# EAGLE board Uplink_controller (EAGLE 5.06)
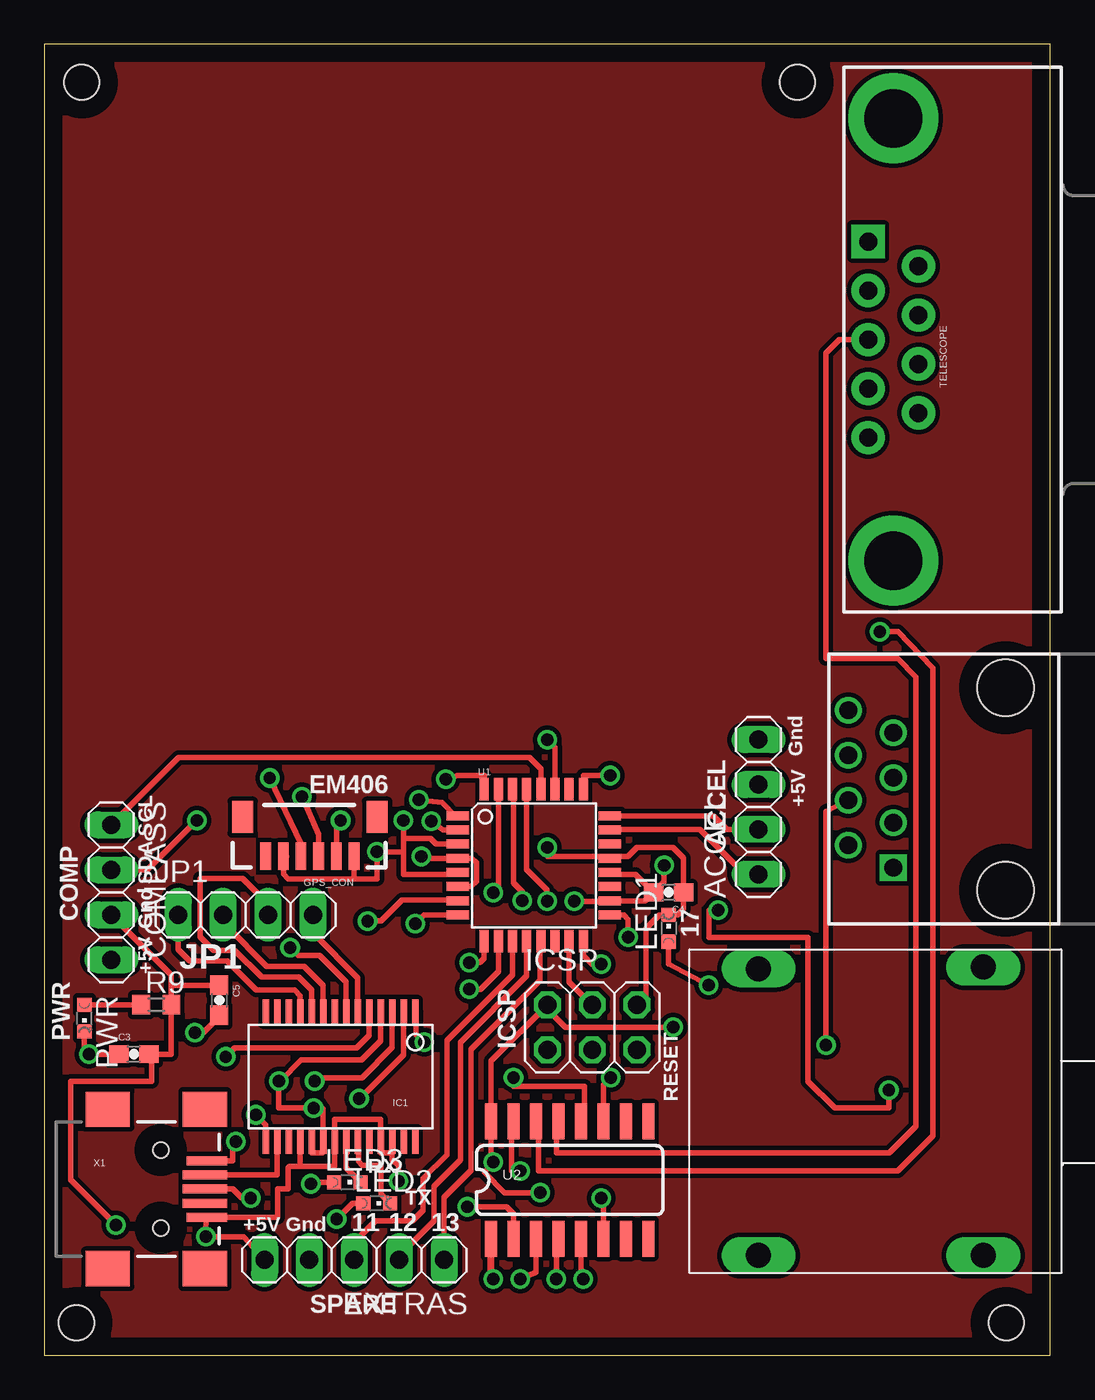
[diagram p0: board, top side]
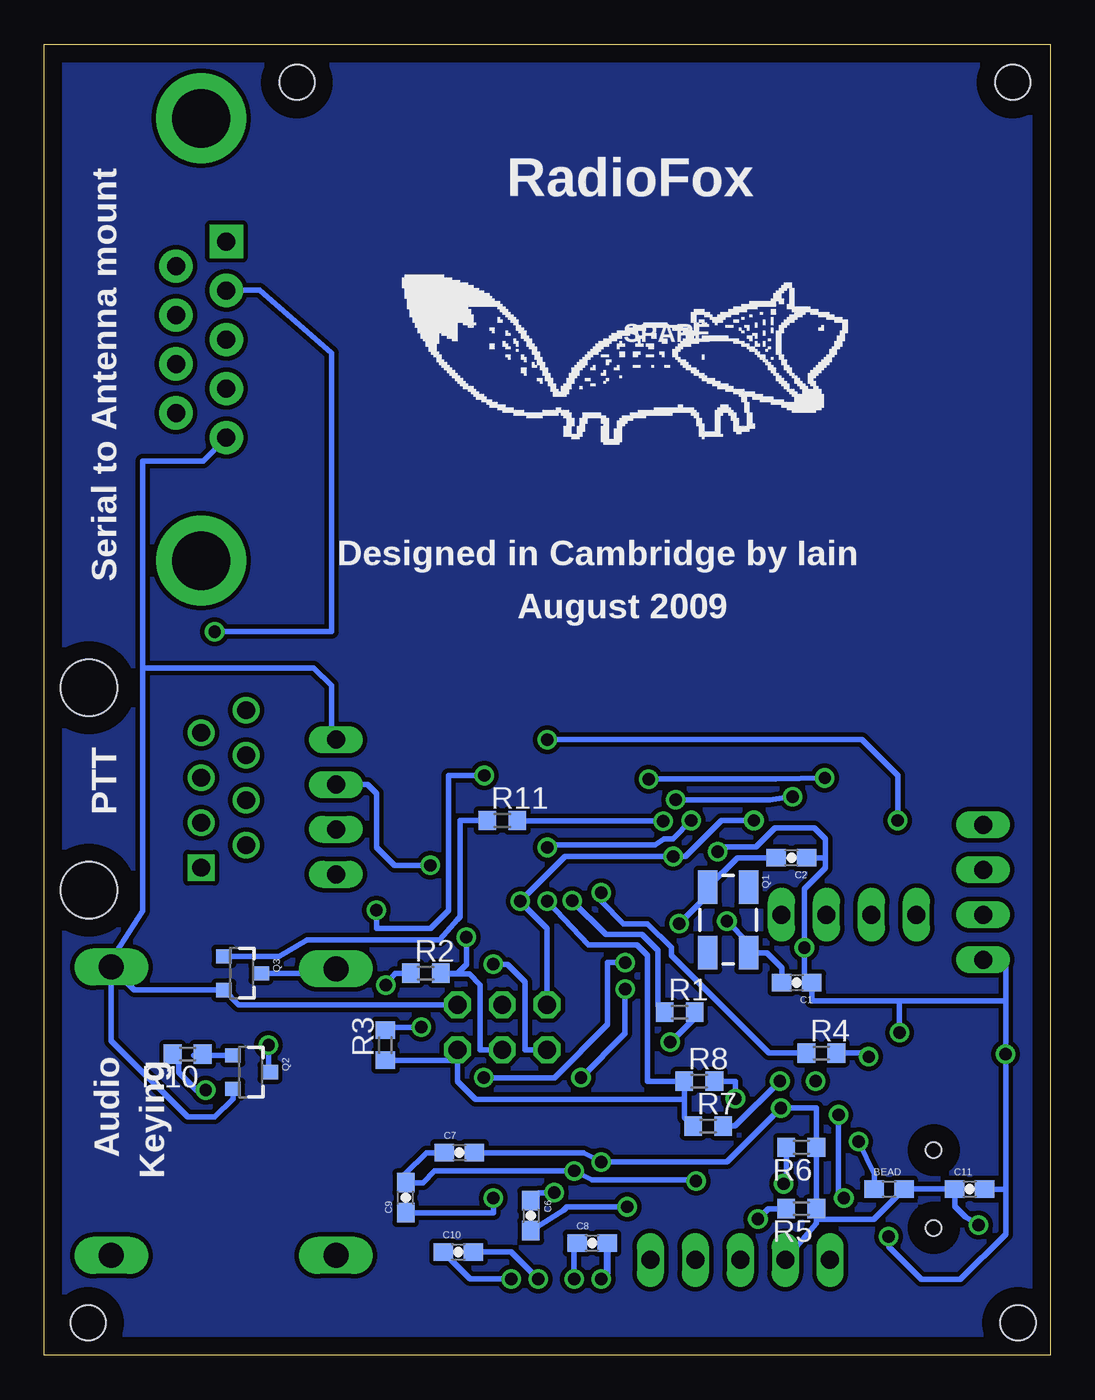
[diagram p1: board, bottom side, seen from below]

Size 56.86 x 74.09 mm. Coordinates in mm from the lower left corner, seen from the top.
Outline: 0,0 56.86,0 56.86,74.09 0,74.09 0,0
Copper layers (1*16): Top 0.035mm / dielectric 1.5mm / Bottom 0.035mm
Design rules "olimex10mils": minimum track width 10mil, minimum drill 24mil, track to track 10mil, track to pad 10mil, pad to pad 10mil, via to via 10mil, smd to smd 10mil, copper to edge 40mil, drill to drill 10mil, minimum pad ring 10mil, minimum via ring 8mil, stop-mask expansion 0mil, vias tented up to drill 0mil, thermal gap 10mil
Holes 2 mm at 42.57,71.94 54.37,1.84 1.82,1.84 2.12,71.94

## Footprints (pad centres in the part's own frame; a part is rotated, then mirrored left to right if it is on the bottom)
1X04 = drill 1.016 long: 1 -3.81,0; 2 -1.27,0; 3 1.27,0; 4 3.81,0
0603 = smd 1.1 x 1: 1 -0.85,0; 2 0.85,0
0603-CAP = smd 1.1 x 1: 1 -0.85,0; 2 0.85,0
1X05 = drill 1.016 long: 1 -5.08,0; 2 -2.54,0; 3 0,0; 4 2.54,0; 5 5.08,0
EM406 = smd 0.6 x 1.55: 1 0,0; 2 1,0; 3 2,0; 4 3,0; 5 4,0; 6 5,0 | smd 1.2 x 1.8: P$1 -1.3,-2.225; P$2 6.3,-2.225
SSOP28DB = smd 0.348 x 1.397: 1 -4.225,-3.656; 2 -3.575,-3.656; 3 -2.925,-3.656; 4 -2.275,-3.656; 5 -1.625,-3.656; 6 -0.975,-3.656; 7 -0.325,-3.656; 8 0.325,-3.656; 9 0.975,-3.656; 10 1.625,-3.656; 11 2.275,-3.656; 12 2.925,-3.656; 13 3.575,-3.656; 14 4.225,-3.656; 15 4.225,3.656; 16 3.575,3.656; 17 2.925,3.656; 18 2.275,3.656; 19 1.625,3.656; 20 0.975,3.656; 21 0.325,3.656; 22 -0.325,3.656; 23 -0.975,3.656; 24 -1.625,3.656; 25 -2.275,3.656; 26 -2.925,3.656; 27 -3.575,3.656; 28 -4.225,3.656
2X03 = drill 1.016 octagon: 1 -2.54,-1.27; 2 -2.54,1.27; 3 0,-1.27; 4 0,1.27; 5 2.54,-1.27; 6 2.54,1.27
AUDIO_JACK_NMJ4HFD2 = drill 1.4 long: 1 0,0; 2 12.7,0.1; 3 0,-16.2; 4 12.7,-16.2
CHIPLED_0603 = smd 0.8 x 0.8: A 0,-0.75; C 0,0.75
CRYSTAL-SMD-5X3 = smd 1.9 x 1.1: 1 -1.85,-1.15; 2 1.85,-1.15; 3 1.85,1.15; 4 -1.85,1.15
SOT23-3 = smd 0.8 x 0.9: 1 -0.95,-1; 2 0.95,-1; 3 0,1.1
R0603 = smd 1 x 1.1: 1 -0.85,0; 2 0.85,0
RJ45-8 = drill 1 square: 1 -4.445,6.35 | drill 1 round: 2 -3.175,8.89; 3 -1.905,6.35; 4 -0.635,8.89; 5 0.635,6.35; 6 1.905,8.89; 7 3.175,6.35; 8 4.445,8.89 | hole 3.2: -5.715,0; 5.715,0
DB9 = drill 1.016 pad 1.88 square: 1 -5.54,-1.42 | drill 1.016 pad 1.88 round: 2 -2.77,-1.42; 3 0,-1.42; 4 2.77,-1.42; 5 5.54,-1.42; 6 -4.15,1.42; 7 -1.38,1.42; 8 1.38,1.42; 9 4.15,1.42 | drill 3.302 pad 5.08 round: G1 -12.5,0; G2 12.5,0
TQFP32-08 = smd 1.27 x 0.508: 1 -4.293,2.8; 2 -4.293,2; 3 -4.293,1.2; 4 -4.293,0.4; 5 -4.293,-0.4; 6 -4.293,-1.2; 7 -4.293,-2; 8 -4.293,-2.8; 17 4.293,-2.8; 18 4.293,-2; 19 4.293,-1.2; 20 4.293,-0.4; 21 4.293,0.4; 22 4.293,1.2; 23 4.293,2; 24 4.293,2.8 | smd 0.508 x 1.27: 9 -2.8,-4.293; 10 -2,-4.293; 11 -1.2,-4.293; 12 -0.4,-4.293; 13 0.4,-4.293; 14 1.2,-4.293; 15 2,-4.293; 16 2.8,-4.293; 25 2.8,4.293; 26 2,4.293; 27 1.2,4.293; 28 0.4,4.293; 29 -0.4,4.293; 30 -1.2,4.293; 31 -2,4.293; 32 -2.8,4.293
SO016 = smd 0.66 x 2.032: 1 -4.445,-3.315; 2 -3.175,-3.315; 3 -1.905,-3.315; 4 -0.635,-3.315; 5 0.635,-3.315; 6 1.905,-3.315; 7 3.175,-3.315; 8 4.445,-3.315; 9 4.445,3.315; 10 3.175,3.315; 11 1.905,3.315; 12 0.635,3.315; 13 -0.635,3.315; 14 -1.905,3.315; 15 -3.175,3.315; 16 -4.445,3.315
USB-MINIB = smd 2.5 x 0.5: D+ 2.5,0; D- 2.5,0.8; ID 2.5,-0.8 | smd 2.3 x 0.5: GND 2.6,-1.6; VBUS 2.6,1.6 | smd 2.5 x 2: GND@1 -3,-4.5; GND@2 -3,4.5; GND@3 2.5,4.5; GND@4 2.5,-4.5 | hole 0.9: 0,2.2; 0,-2.2

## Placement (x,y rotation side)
ACCEL  [1X04]  40.37,30.99 90 top
BEAD  [0603]  9.11,9.4 0 bottom
C1  22p  [0603-CAP]  14.33,21.05 180 bottom
C2  22p  [0603-CAP]  14.63,28.11 180 bottom
C3  100n  [0603-CAP]  5.06,17.02 0 top
C4  100n  [0603-CAP]  35.29,26.16 180 top
C5  10n  [0603-CAP]  9.89,20.06 270 top
C6  1u  [0603-CAP]  29.36,7.89 270 bottom
C7  1u  [0603-CAP]  33.39,11.45 0 bottom
C8  1u  [0603-CAP]  25.89,6.34 0 bottom
C9  1u  [0603-CAP]  36.43,8.9 90 bottom
C10  1u  [0603-CAP]  33.46,5.84 0 bottom
C11  10u  [0603-CAP]  4.56,9.4 0 bottom
COMPASS  [1X04]  3.79,26.16 270 top
EXTRAS  [1X05]  17.52,5.39 180 top
GPS_CON  EM406  [EM406]  17.51,28.19 180 top
IC1  FT232RLSSOP  [SSOP28DB]  16.75,15.75 180 top
ICSP  [2X03]  30.97,18.54 0 top
JACK1  AUDIO_JACK  [AUDIO_JACK_NMJ4HFD2]  40.37,21.84 0 top
JP1  [1X04]  11.38,24.89 0 top
LED1  [CHIPLED_0603]  35.29,24.13 0 top
LED2  [CHIPLED_0603]  18.79,8.59 270 top
LED3  [CHIPLED_0603]  17.14,9.78 270 top
PWR  [CHIPLED_0603]  2.27,19.05 180 top
Q1  16MHz  [CRYSTAL-SMD-5X3]  18.2,24.61 270 bottom
Q2  MOSFET-NCHANNELSMD  [SOT23-3]  45.2,16 270 bottom
Q3  MOSFET-NCHANNELSMD  [SOT23-3]  45.7,21.59 270 bottom
R1  1K  [R0603]  20.95,19.4 0 bottom
R2  1K  [R0603]  35.29,21.59 0 bottom
R3  10K  [R0603]  37.58,17.52 90 bottom
R4  1K  [R0603]  12.94,17.08 0 bottom
R5  1K  [R0603]  14.07,8.29 180 bottom
R6  1K  [R0603]  14.07,11.75 180 bottom
R7  100R  [R0603]  19.34,12.95 0 bottom
R8  100R  [R0603]  19.84,15.49 0 bottom
R9  1K  [R0603]  6.33,19.81 0 top
R10  1K  [R0603]  48.75,17.02 180 bottom
R11  1K  [R0603]  30.97,30.22 0 bottom
RADIO_MIKE  RJ45-8PTH  [RJ45-8]  54.34,32 90 top
TELESCOPE  [DB9]  47.99,57.4 270 top
U1  ATMEGA168  [TQFP32-08]  27.67,27.68 0 top
U2  MAX232SOIC16  [SO016]  29.7,9.9 0 top
U$7  EM406_OUTLINE  [EM406_OUTLINE]  not placed on the board
X1  USBSMD  [USB-MINIB]  6.59,9.4 0 top

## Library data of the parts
ACCEL COMPASS EXTRAS ICSP JP1 = pinhead
BEAD C1-C11 GPS_CON IC1 Q1-Q3 RADIO_MIKE TELESCOPE U1 U2 U$7 X1 = SparkFun
JACK1 = uplink_controller
LED1-LED3 PWR = led
R1-R11 = rcl

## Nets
5V: ACCEL.3 BEAD.2 C3.2 C4.2 C5.1 C6.1 C7.2 C11.1 COMPASS.3 EXTRAS.4 GPS_CON.2 IC1.4 IC1.19 IC1.20 ICSP.2 R3.2 R5.1 R6.1 R9.2 U1.4 U1.6 U1.18 U1.20 U2.16
EXTRA1: EXTRAS.3 U1.11
EXTRA2: EXTRAS.2 U1.12
EXTRA3: EXTRAS.1 U1.13
GND: ACCEL.4 C1.1 C2.1 C3.1 C4.1 C5.2 C7.1 C9.2 C11.2 COMPASS.4 EXTRAS.5 GPS_CON.1 GPS_CON.5 IC1.7 IC1.18 IC1.21 IC1.25 IC1.26 ICSP.6 JACK1.2 LED1.C PWR.C Q2.2 Q3.2 TELESCOPE.5 U1.3 U1.5 U1.21 U2.15 X1.GND
GPS_ATM168_RX: GPS_CON.4 U1.32
GPS_ATM168_TX: GPS_CON.3 U1.1
KEY_OUT: R11.2 U1.2
N$1: C1.2 Q1.3 U1.7
N$2: C2.2 Q1.1 U1.8
N$3: ICSP.1 U1.16
N$4: LED1.A R2.1
N$5: ICSP.3 R2.2 U1.17
N$6: IC1.1 R1.2
N$7: IC1.5 R4.2
N$8: LED2.A R5.2
N$9: IC1.23 LED2.C
N$10: IC1.22 LED3.C
N$11: LED3.A R6.2
N$12: IC1.16 X1.D-
N$13: IC1.15 X1.D+
N$14: TELESCOPE.3 U2.13
N$15: IC1.6 JP1.4
N$16: IC1.10 JP1.3
N$17: IC1.9 JP1.2
N$18: IC1.11 JP1.1
N$19: IC1.3 R7.2
N$20: IC1.2 R8.2
N$21: Q2.3 RADIO_MIKE.4
N$22: JACK1.1 Q3.3
N$23: ICSP.4 U1.15
N$24: PWR.A R9.1
N$25: Q2.1 R10.1
N$26: C8.2 U2.1
N$27: COMPASS.1 U1.28
N$28: COMPASS.2 U1.27
N$29: C8.1 U2.3
N$30: ACCEL.1 U1.23
N$31: C10.2 U2.4
N$32: C10.1 U2.5
N$33: C9.1 U2.6
N$34: C6.2 U2.2
N$35: Q3.1 R11.1
N$36: BEAD.1 X1.VBUS
N$39: U1.26
N$40: U1.19
N$41: U1.22
N$42: ACCEL.2 U1.24
PTT: R10.2 U1.25
RAND: TELESCOPE.2 U2.14
RESET: ICSP.5 R3.1 R7.1 R8.1 U1.29
SERIAL_RX: R4.1 U1.31
SERIAL_TX: R1.1 U1.30
TELESC_ATM168_RX: U1.10 U2.12
TELESC_ATM168_TX: U1.9 U2.11

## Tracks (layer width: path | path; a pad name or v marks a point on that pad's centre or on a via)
5V  (via drill 0.7)
  Top 0.305: IC1.19 15.12,11.43 15.73,11.43 15.73,12.09 IC1.20 15.77,13.93 v15.22,13.97 13.26,13.97 v13.26,15.49 13.33,15.49 14.52,16.69 17.94,16.69 19.02,17.77 IC1.4 | v29.96,25.65 31.93,25.65 arc90 U1.18 33.96,25.68 C4.2 | v21.32,28.19 21.72,28.08 U1.4 24.18,28.08 24.42,27.84 24.42,26.79 24.12,26.49 U1.6 | GPS_CON.2 16.51,30.22 v16.75,30.22 | v35.54,18.54 29.45,18.54 28.43,19.56 ICSP.2 25.26,16.63 U2.16 25.26,11.04 v25.38,10.92 24.88,10.34 26.02,9.19 v28.02,9.19 | R9.2 7.18,20.91 | 7.18,20.91 C5.1 | R9.2 7.44,19.56 | v4.05,7.36 1.51,9.9 1.51,15.49 6.08,15.49 6.08,17.02 C3.2 7.18,17.02 R9.2 | COMPASS.3 7.18,21.5 7.18,20.91 | U1.20 32.07,27.18 33.42,27.18 C4.2 | C4.2 35.04,26.76 v35.04,27.68
  Bottom 0.305: C7.2 26.38,11.45 v25.38,10.92 18.27,10.92 v15.22,13.97 13.22,13.97 R6.1 R5.1 | ICSP.2 28.43,24.13 v29.96,25.65 27.42,28.19 v21.32,28.19 20.62,28.19 18.59,30.22 v16.75,30.22 | R3.2 37.41,18.54 v35.54,18.54 | v35.04,27.68 37.07,27.68 38.08,28.7 38.08,31.75 38.59,32.26 ACCEL.3 | v4.05,7.36 4.81,7.81 5.41,8.41 C11.1 | R5.1 13.22,7.69 9.97,7.69 BEAD.2 C11.1 | C6.1 28.91,9.19 v28.02,9.19 | EXTRAS.4 13.22,7.45 R5.1 | C11.1 5.15,9.14
EXTRA1
  Top 0.305: U1.11 26.47,21.48 22.77,17.79 22.77,11.34 21.42,9.99 21.42,8.19 20.82,7.59 18.72,7.59 17.82,6.69 17.82,5.99 EXTRAS.3
EXTRA2
  Top 0.305: U1.12 27.27,21.43 23.52,17.69 23.52,11.04 22.02,9.54 22.02,7.59 20.12,5.69 EXTRAS.2 20.02,5.73
EXTRA3
  Top 0.305: U1.13 28.02,23.39 28.02,21.19 24.12,17.29 24.12,10.44 22.6,8.92 EXTRAS.1
GND  (via drill 0.7)
  Top 0.305: 14.47,10.69 IC1.18 | 19.67,11.43 19.02,11.43 IC1.25 19.02,13.34 16.42,13.34 IC1.21 16.42,10.69 14.47,10.69 | 19.67,11.43 IC1.26 | U2.15 26.4,13.09 26.4,10.42 v26.9,10.42 | 19.67,11.43 19.67,11.04 20.02,10.69 v20.02,9.84 | ICSP.6 34.02,20.32 34.02,24.13 34.77,24.88 LED1.C 35.79,24.88 36.14,25.23 C4.1 36.14,28.1 35.54,28.7 33.51,28.7 33,28.19 32.07,28.19 U1.21 31.96,28.19 28.43,28.19 v28.43,28.7 | 17.51,26.92 GPS_CON.1 | 20.3,28.44 20.3,29.21 | 20.3,28.44 20.3,27.18 23.27,27.18 U1.5 | 20.3,29.21 21.83,29.21 22.15,28.88 U1.3 | 20.3,29.21 v20.3,30.22 | PWR.C 2.27,17.02 v2.52,17.02 C3.1 | GPS_CON.5 13.7,28.19 13.52,28.02 13.52,27.19 13.79,26.92 17.51,26.92 | C5.2 9.98,19.21 9,18.24 v8.52,18.24 | EXTRAS.5 11.28,6.71 v9.13,6.71 9.09,6.9 X1.GND 13.19,7.8 13.19,9.4 13.77,9.4 13.77,10.59 13.87,10.69 14.47,10.69 | 20.3,28.44 18.83,28.44 v18.8,28.47 18.8,26.92 17.51,26.92 | IC1.7 17.07,21.09 15.57,22.59 14.34,22.59 v13.9,23.03
  Bottom 0.305: JACK1.2 51.77,20.64 Q3.2 45.88,19.81 ICSP.6 | Q2.2 46.2,14.49 47.23,13.46 48.75,13.46 53.07,17.78 JACK1.2 | COMPASS.4 2.52,22.35 2.52,20.04 | 2.52,20.04 v2.52,17.02 2.52,9.39 | TELESCOPE.5 47.89,50.54 51.3,50.54 51.3,38.85 | 51.3,38.85 51.3,25.12 53.07,22.35 JACK1.2 | ACCEL.4 40.62,35.05 40.62,37.84 41.63,38.85 51.3,38.85 | v9.13,6.71 9.13,6.14 7.27,4.29 5.07,4.29 2.52,6.84 2.52,9.39 | C7.1 35.26,11.45 36.43,10.28 C9.2 35.46,9.75 34.79,10.42 v26.9,10.42 25.9,9.92 20.02,9.92 v20.02,9.84 | 12.72,28.14 12.72,27.54 13.9,26.36 v13.9,23.03 13.9,21.36 13.48,20.94 | 12.72,28.14 12.72,29.19 13.32,29.79 15.57,29.79 16.62,28.74 18.53,28.74 v18.8,28.47 | C2.1 12.75,28.11 12.72,28.14 | 13.48,20.94 C1.1 | 13.48,20.94 13.47,20.94 | C11.2 2.52,9.39 | v28.43,28.7 28.28,28.85 22.34,28.85 21.85,29.19 21.34,29.19 v20.3,30.22 | 13.48,20.94 13.48,20.04 8.52,20.04 | 2.52,20.04 8.52,20.04 | 8.52,20.04 v8.52,18.24
GPS_ATM168_RX  (via drill 0.7)
  Top 0.305: GPS_CON.4 14.51,28.91 v12.74,32.62 | v22.69,32.56 23.35,32.76 24.88,32.76 24.87,32.76 U1.32
  Bottom 0.305: v22.69,32.56 15.52,32.56 v12.74,32.62
GPS_ATM168_TX  (via drill 0.7)
  Top 0.305: GPS_CON.3 15.51,29.43 v14.57,31.57 | v21.17,31.39 22.47,31.24 23.23,30.48 U1.1
  Bottom 0.305: v21.17,31.39 15.88,31.39 v14.57,31.57
KEY_OUT  (via drill 0.7)
  Top 0.305: U1.2 22.53,29.68 v21.87,30.19
  Bottom 0.305: v21.87,30.19 30.09,30.19 R11.2
N$1  (via drill 0.7)
  Top 0.305: U1.7 23.32,25.74 20.22,25.74 19.02,24.54 v18.27,24.54
  Bottom 0.305: C1.2 15.18,21.89 16.02,22.74 17.03,22.74 Q1.3 17.05,23.31 v18.27,24.54
N$2  (via drill 0.7)
  Top 0.305: v20.97,24.39 21.47,24.88 U1.8
  Bottom 0.305: C2.2 17.69,28.11 Q1.1 19.35,26.01 v20.97,24.39
N$3  (via drill 0.7)
  Top 0.305: U1.16 30.46,22.6 30.97,22.1 v31.48,22.1
  Bottom 0.305: ICSP.1 29.67,17.27 29.67,21.09 30.68,22.1 v31.48,22.1
N$4  (via drill 0.7)
  Top 0.305: LED1.A 35.29,22.11 v37.56,20.91
  Bottom 0.305: v37.56,20.91 37.04,21.59 R2.1
N$5  (via drill 0.7)
  Top 0.305: v33,23.62 33,24.64 32.76,24.88 U1.17
  Bottom 0.305: v33,23.62 33,22.1 33.51,21.59 R2.2 34.39,21.54 32.82,21.54 32.22,20.94 32.22,17.27 ICSP.3
N$6  (via drill 0.7)
  Top 0.305: IC1.1 21.02,19.4 21.02,18.14 v21.47,17.69
  Bottom 0.305: R1.2 20.1,19.07 v21.47,17.69
N$7  (via drill 0.7)
  Top 0.305: v10.26,16.87 10.76,17.37 17.66,17.37 18.37,18.09 IC1.5
  Bottom 0.305: v10.26,16.87 10.47,17.08 R4.2
N$8  (via drill 0.7)
  Top 0.305: LED2.A 17.42,8.59 v16.52,7.69
  Bottom 0.305: R5.2 15.92,8.29 v16.52,7.69
N$9
  Top 0.305: IC1.23 17.72,11.43 17.76,11.43 17.76,10.95 17.97,10.74 18.97,10.74 19.02,10.69 19.02,9.1 LED2.C
N$10
  Top 0.305: IC1.22 17.07,10.59 LED3.C
N$11  (via drill 0.7)
  Top 0.305: LED3.A 15.16,9.78 v15.07,9.69
  Bottom 0.305: R6.2 14.92,9.84 v15.07,9.69
N$12
  Top 0.305: 13.17,11.43 13.17,10.67 | 13.17,11.43 IC1.16 | X1.D- 13.17,10.2 13.17,11.43
N$13  (via drill 0.7)
  Top 0.305: X1.D+ 10.65,9.4 11.16,8.89 v11.67,8.89 | IC1.15 12.52,13.03 v11.97,13.59
  Bottom 0.305: v11.97,13.59 11.97,9.19 v11.67,8.89
N$14
  Top 0.305: U2.13 28.94,13.09 28.94,11.43 47.75,11.43 49.27,12.94 49.27,38.34 48.24,39.37 44.18,39.37 44.18,56.64 44.94,57.4 TELESCOPE.3
N$15
  Top 0.305: IC1.6 17.72,21.34 15.27,23.79 15.27,24.81 JP1.4
N$16
  Top 0.305: IC1.10 15.12,20.64 14.37,21.39 12.27,21.39 10.77,22.89 9.57,22.89 8.82,23.64 8.82,26.94 11.22,26.94 12.72,25.44 12.72,24.96 JP1.3
N$17
  Top 0.305: IC1.9 15.77,20.89 14.67,21.99 12.57,21.99 10.32,24.24 10.32,24.68 JP1.2
N$18
  Top 0.305: IC1.11 14.47,20.31 14.14,20.64 11.97,20.64 10.32,22.29 8.22,22.29 7.57,22.94 JP1.1
N$19  (via drill 0.7)
  Top 0.305: IC1.3 19.67,17.4 17.96,15.69 15.48,15.69 v15.28,15.48
  Bottom 0.305: R7.2 17.81,12.95 v15.28,15.48
N$20  (via drill 0.7)
  Top 0.305: IC1.2 20.32,16.99 17.84,14.5 v17.8,14.5
  Bottom 0.305: v17.8,14.5 17.79,15.49 R8.2
N$21  (via drill 0.7)
  Top 0.305: v44.18,17.52 44.18,30.73 RADIO_MIKE.4
  Bottom 0.305: Q2.3 44.18,16 v44.18,17.52
N$22
  Bottom 0.305: Q3.3 40.62,21.59 JACK1.1
N$23
  Top 0.305: U1.15 29.67,21.11 ICSP.4
N$24
  Top 0.305: PWR.A 5.47,19.8 R9.1
N$25
  Bottom 0.305: R10.1 48.41,16.95 Q2.1
N$26  (via drill 0.7)
  Top 0.406: U2.1 25.26,4.44 v25.38,4.32
  Bottom 0.406: v25.38,4.32 25.04,4.66 C8.2
N$27
  Top 0.305: COMPASS.1 7.6,33.78 27.42,33.78 28.07,33.13 U1.28
N$28  (via drill 0.7)
  Top 0.305: COMPASS.2 5.83,27.43 v8.62,30.22 | v28.43,34.8 28.87,34.36 U1.27
  Bottom 0.305: v8.62,30.22 8.62,32.76 10.65,34.8 v28.43,34.8
N$29  (via drill 0.7)
  Top 0.305: U2.3 27.8,4.7 v26.91,4.32
  Bottom 0.305: C8.1 26.91,6.17 v26.91,4.32
N$30
  Top 0.305: U1.23 32,29.72 37.07,29.72 39.61,27.18 ACCEL.1
N$31  (via drill 0.7)
  Top 0.305: v28.94,4.32 28.94,6.46 U2.4
  Bottom 0.305: v28.94,4.32 30.46,5.84 C10.2
N$32  (via drill 0.7)
  Top 0.305: U2.5 30.34,4.95 v30.46,4.32
  Bottom 0.305: C10.1 32.78,4.32 v30.46,4.32
N$33  (via drill 0.7)
  Top 0.305: v31.48,8.89 31.61,8.76 U2.6
  Bottom 0.305: C9.1 31.48,8.05 v31.48,8.89
N$34  (via drill 0.7)
  Top 0.305: U2.2 26.53,8 26.14,8.39 v23.9,8.39
  Bottom 0.305: C6.2 27.52,8.19 27.32,8.39 v23.9,8.39
N$35
  Bottom 0.305: Q3.1 43.59,22.54 42,23.47 34.53,23.47 33.51,24.64 33.36,24.79 33.36,30.22 R11.1
N$36  (via drill 0.7)
  Top 0.305: X1.VBUS 10.65,11 10.65,11.94 v10.84,12.09
  Bottom 0.305: v10.84,12.09 9.94,10.22 BEAD.1
N$37
  pour Bottom (isolate 0.254): -0.13,74.34 0.02,0.19 56.87,0.19 57.02,74.19
N$38
  pour Top (isolate 0.254): 0.02,74.19 0.02,0.19 56.72,0.19 57.02,74.19
N$42
  Top 0.305: ACCEL.2 38.59,29.72 37.82,30.48 U1.24
PTT  (via drill 0.7)
  Top 0.305: U1.25 30.46,32.76 v31.99,32.76 | v47.74,14.98 47.74,13.97 44.69,13.97 43.16,15.49 43.16,23.62 37.58,23.62 37.58,25.14 v38.08,25.14
  Bottom 0.305: v47.74,14.98 48.24,14.98 49.26,16 49.26,16.67 R10.2 | v38.08,25.14 38.08,24.13 35.04,24.13 34.02,25.14 34.02,32.76 v31.99,32.76
RAND  (via drill 0.7)
  Top 0.305: U2.14 27.92,13.09 27.92,10.41 48.25,10.41 50.23,12.4 50.23,38.85 48.24,40.89 v47.23,40.89 | TELESCOPE.2 46.55,60.2
  Bottom 0.305: v47.23,40.89 40.62,40.89 40.62,56.64 44.69,60.2 46.55,60.2 TELESCOPE.2
RESET  (via drill 0.7)
  Top 0.305: v28.42,25.65 28.42,26.29 27.27,27.44 U1.29
  Bottom 0.305: R3.1 33.51,16.67 ICSP.5 33.51,15.49 32.5,14.48 20.69,14.48 R8.1 | R7.1 20.69,13.45 R8.1 | R8.1 20.83,15.49 | v28.42,25.65 26.11,23.19 23.37,23.19 22.77,22.59 22.77,15.49 R8.1
SERIAL_RX  (via drill 0.7)
  Top 0.305: v25.38,26.15 25.67,26.45 U1.31
  Bottom 0.305: R4.1 15.91,17.08 21.42,22.59 21.42,23.04 22.77,24.39 24.12,24.39 25.38,25.64 v25.38,26.15
SERIAL_TX  (via drill 0.7)
  Top 0.305: U1.30 26.52,31.98 26.52,26.69 27.02,26.19 v27.02,25.69
  Bottom 0.305: v27.02,25.69 25.12,23.79 23.07,23.79 22.17,22.89 22.17,19.78 R1.1
TELESC_ATM168_RX  (via drill 0.7)
  Top 0.305: U2.12 30.52,13.41 30.52,15.19 26.52,15.19 v26.52,15.69 | U1.10 25.67,21.69 24.67,20.69 v24.02,20.69
  Bottom 0.305: v24.02,20.69 24.02,18.19 v26.52,15.69
TELESC_ATM168_TX  (via drill 0.7)
  Top 0.305: v32.02,15.69 31.61,15.27 U2.11 | U1.9 24.87,22.43 24.62,22.19 v24.02,22.19
  Bottom 0.305: v32.02,15.69 28.02,15.69 25.02,18.69 25.02,22.19 v24.02,22.19

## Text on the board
tPlace: Gnd | EM406 | +5V | SCL | ACCEL | SDA | COMP | Gnd | Gnd | 17 | JP1 | +5V | PWR | ICSP | RESET | RX | TX | +5V | Gnd | 11 | 12 | 13 | SPARE
bPlace: RadioFox | SPARE | Designed in Cambridge by Iain | Serial to Antenna mount | August 2009 | PTT | Audio | Keying
_tsilk: Gnd | EM406 | +5V | SCL | SDA | ACCEL | COMP | Gnd | 17 | JP1 | +5V | +5V | Gnd | PWR | ICSP | RESET | RX | Gnd | +5V | 11 | TX | 12 | 13 | SPARE
_bsilk: RadioFox | Uplink and Antenna Control | Serial to Aerial Mount | Designed in Cambridge by Iain | August 2009 | PTT | Keying | Radio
